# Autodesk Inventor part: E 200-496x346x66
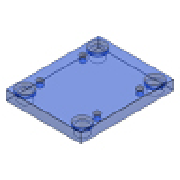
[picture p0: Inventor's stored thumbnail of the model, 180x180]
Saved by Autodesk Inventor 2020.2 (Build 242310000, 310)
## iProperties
Manager: www.cadconsulting.pl
Company: Fabian Stasiak CAD Consulting
Created: 2014-02
Part Number: E 200-496x346x66
Material: S 55 C
Description: Cavity Plate
Document SubType Name: Modeling
Designer: F.Stasiak
Standard Revision: 1
Manufacturer: DME
Language: pl-PL
Size Designation: 496x346x66
Categories: <MemberInstance><Categories><Category DisplayName="Forma wtryskowa" InternalName="349578f2-f4d4-4954-8c09-8e99297a61c0" Mnemonic="MOLD"><Category DisplayName="P
Density: 7.85 g/cm^3
Appearance: Clear - Blue
Catalog Web Link: www.expertbooks.pl
IsCustomPart: 1
Author: F.Stasiak
Subject: Zbiór ćwiczeń. Autodesk Inventor 2020. Kurs Professional
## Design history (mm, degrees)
sketch "Sketch1"
  geometry: L1 (-173, 248)-(173, 248); L2 (173, 248)-(173, -248); L3 (173, -248)-(-173, -248); L4 (-173, -248)-(-173, 248); 3 further points
  constraints: 8 end point, 2 midpoint, 2 parallel, 1 horizontal, 1 horizontal alignment, 1 perpendicular, 1 vertical alignment
  dimensions: "d126" = 346 distance between parallel lines of L2 L4 (= W_); "d127" = 496 distance between parallel lines of L3 L1 (= L)
extrude "Extrusion1" new body sketch "Sketch1" distance "d20" = 66 (= H_); taper "d30" = 0 deg
sketch "Sketch2"
  geometry: 3 further points
  dimensions: "d128" = 137 horizontal distance of point (0, 0) point (-137, 165) (= 0.5 x S1_W); "d129" = 165 vertical distance of point (0, 0) point (-137, 165) (= 0.5 x S1_L); "d130" = 208 vertical distance of point (0, 0) point (-137, 208) (= 0.5 x GP_L); "d131" = 137 horizontal distance of point (0, 0) point (-137, 208) (= 0.5 x GP_W)
hole "Hole1" sketch "Sketch2" diameter "d132" = 42 (= GP_d1); stored, may be unused: countersink angle "d136" = 90 deg, drill point angle "d138" = 0 deg; dims "d133" = 6, "d134" = 48 (= GP_d2), "d135" = 6 (= GP_k), "d137" = 66 (= H_)
pattern_linear "Rectangular Pattern1" dims "d148" = 416 (computed from GP_L, Nl), "d151" = 274 (computed from GP_W, Nw)
hole "Hole2" sketch "Sketch2" diameter "d139" = 13.835; stored, may be unused: countersink angle "d143" = 90 deg, drill point angle "d145" = 118 deg; dims "d140" = 24.5 (= H_l), "d141" = 48 (= GP_d2), "d142" = 6 (= GP_k), "d144" = 25 (= H_u)
pattern_linear "Rectangular Pattern2" dims "d154" = 330 (computed from S1_L, Ns), "d157" = 274 (computed from S1_W, Nw)
chamfer "Chamfer1" distance "d158" = 0.5; stored, may be unused: second distance "d159" = 2, angle "d160" = 45 deg
sketch "Szkic3"
  geometry: L1 (-78, -154.488)-(-78, 154.488); L2 (72.488, -160)-(-72.488, -160); L3 (78, 154.488)-(78, -154.488); L4 (-72.488, 160)-(72.488, 160); A1 r 4 centre (-75.879, 157.879) between (-72.488, 160) and (-78, 154.488); A2 r 4 centre (-75.879, -157.879) between (-78, -154.488) and (-72.488, -160); A3 r 4 centre (75.879, -157.879) between (72.488, -160) and (78, -154.488); A4 r 4 centre (75.879, 157.879) between (78, 154.488) and (72.488, 160)
  constraints: 8 end point, 8 point on circle, 4 centre point
extrude "Wyciągnięcie proste2" cut sketch "Szkic3" distance "d162" = 60; taper "d163" = 0 deg
node "Płaszczyzna konstrukcyjna2"
node "Płaszczyzna konstrukcyjna3"
node "Płaszczyzna konstrukcyjna4"
node "Płaszczyzna konstrukcyjna5"
node "Płaszczyzna konstrukcyjna6"
node "Płaszczyzna konstrukcyjna7"
node "Płaszczyzna konstrukcyjna8"
node "Płaszczyzna konstrukcyjna9"
feature "Rzeźbienie9"
feature "Rzeźbienie10"
feature "Rzeźbienie11"
feature "Rzeźbienie12"
feature "Rzeźbienie13"
feature "Rzeźbienie14"
feature "Rzeźbienie15"
feature "Rzeźbienie16"
feature "Rzeźbienie17"
feature "Rzeźbienie18"
feature "Rzeźbienie19"
body "Solid1"
feature "Powierzchnia9"
body "Srf9"
feature "Powierzchnia10"
body "Srf10"
feature "Powierzchnia11"
body "Srf11"
feature "Powierzchnia12"
body "Srf12"
feature "Powierzchnia13"
body "Srf13"
feature "Powierzchnia14"
body "Srf14"
feature "Powierzchnia15"
body "Srf15"
feature "Powierzchnia16"
body "Srf16"
feature "Powierzchnia17"
body "Srf17"
feature "Powierzchnia18"
body "Srf18"
feature "Powierzchnia19"
body "Srf19"
other parameters: "L" = 496 [user parameter; used in 1 equation term], "W_" = 346 [user parameter; used in 1 equation term], "H_" = 66 [user parameter; used in 2 equation terms], "GP_W" = 274 [user parameter; used in 2 equation terms], "GP_d1" = 42 [user parameter; used in 1 equation term], "GP_d2" = 48 [user parameter; used in 2 equation terms], "GP_k" = 6 [user parameter; used in 2 equation terms], "S1_W" = 274 [user parameter; used in 2 equation terms], "GP_L" = 416 [user parameter; used in 2 equation terms], "H_u" = 25 [user parameter; used in 1 equation term], "H_l" = 24.5 [user parameter; used in 1 equation term], "d161" = -20.1915
